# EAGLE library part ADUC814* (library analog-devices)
MicroConverter® 12-Bit ADC with Embedded FLASH MCU Small Package
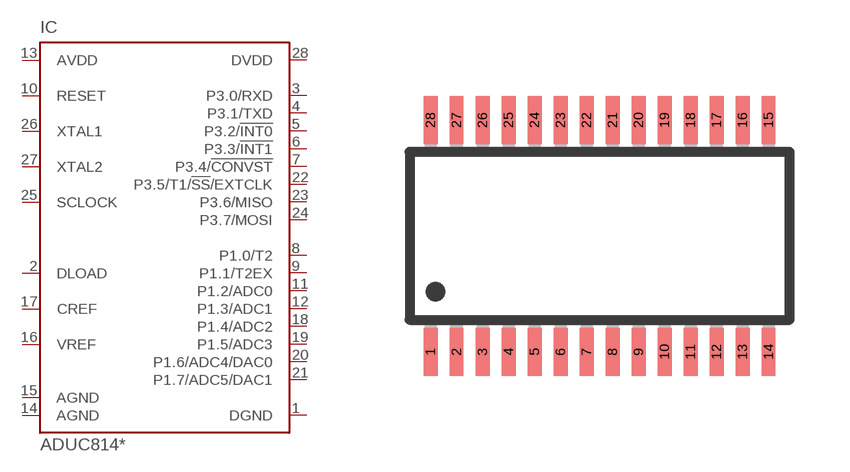
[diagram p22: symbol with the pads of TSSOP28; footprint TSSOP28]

Designator prefix IC

## ADUC814ARU (MPN: ADUC814ARUZ; OC_FARNELL: 9426361; OC_NEWARK: 31M3924), ADUC814BRU (MPN: ADUC814BRU; OC_FARNELL: 1424536; OC_NEWARK: 92C2265)  [TSSOP28]
1  DGND  pwr
2  DLOAD  in
3  P3.0/RXD
4  P3.1/TXD
5  P3.2/!INT0
6  P3.3/!INT1
7  P3.4/!CONVST
8  P1.0/T2
9  P1.1/T2EX
10  RESET  in
11  P1.2/ADC0
12  P1.3/ADC1
13  AVDD  pwr
14  AGND  pwr
15  AGND  pwr
16  VREF  pas
17  CREF  pas
18  P1.4/ADC2
19  P1.5/ADC3
20  P1.6/ADC4/DAC0
21  P1.7/ADC5/DAC1
22  P3.5/T1/!SS!/EXTCLK
23  P3.6/MISO
24  P3.7/MOSI
25  SCLOCK
26  XTAL1
27  XTAL2
28  DVDD  pwr

## Footprint TSSOP28 (pad centres in mm)
28-Lead TSSOP Package RU-28
smd 0.35 x 1.2: 1 -4.225,-2.9; 2 -3.575,-2.9; 3 -2.925,-2.9; 4 -2.275,-2.9; 5 -1.625,-2.9; 6 -0.975,-2.9; 7 -0.325,-2.9; 8 0.325,-2.9; 9 0.975,-2.9; 10 1.625,-2.9; 11 2.275,-2.9; 12 2.925,-2.9; 13 3.575,-2.9; 14 4.225,-2.9; 15 4.225,2.9; 16 3.575,2.9; 17 2.925,2.9; 18 2.275,2.9; 19 1.625,2.9; 20 0.975,2.9; 21 0.325,2.9; 22 -0.325,2.9; 23 -0.975,2.9; 24 -1.625,2.9; 25 -2.275,2.9; 26 -2.925,2.9; 27 -3.575,2.9; 28 -4.225,2.9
